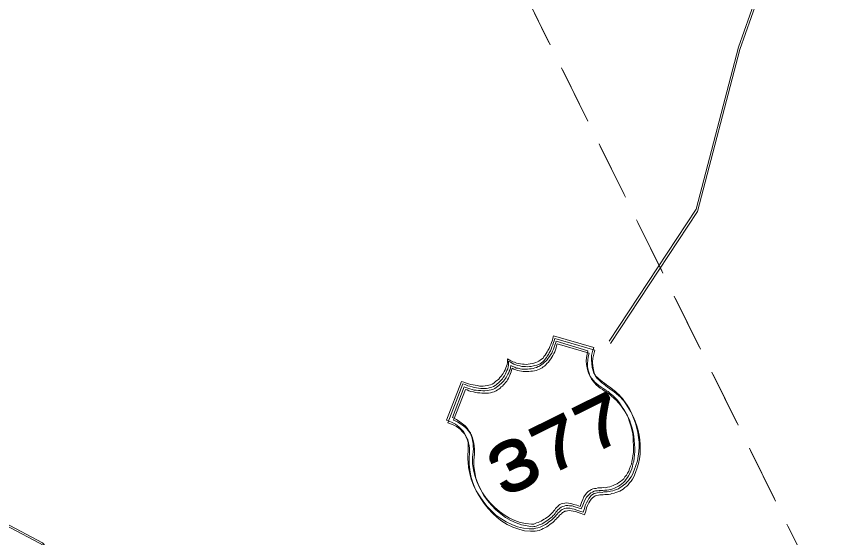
# Model space of a CAD drawing. Extents: x 2356606 to 2371222, y 6973096 to 6982644.
# Drawn here: x 2357158.9 to 2357247.4, y 6973509.1 to 6973564.3 of the extents above; entities that cross this region are included whole.
import ezdxf

# ---------------------------------------------------------------- set-up
doc = ezdxf.new("R2010")
doc.units = 0
doc.header["$LTSCALE"] = 2
doc.linetypes.add('MEDIUM_DASHED', pattern=[4.5, 3, -1.5])
doc.layers.add('62', color=7, linetype='Continuous', lineweight=13)
doc.layers.add('63', color=7, linetype='Continuous', lineweight=13)

msp = doc.modelspace()

# ---------------------------------------------------------------- linework, layer by layer
at = {"layer": '62', "linetype": 'MEDIUM_DASHED'}
msp.add_line((2357160.992, 6973671.606), (2357243.202, 6973505.087), dxfattribs=at)
at = {"layer": '62'}
msp.add_line((2357231.053, 6973543.631), (2357221.833, 6973529.622), dxfattribs=at)
for points in [[(2357247.334, 6973598.086), (2357243.665, 6973587.068), (2357241.545, 6973577.843), (2357235.54, 6973560.823), (2357231.053, 6973543.631)], [(2357204.57, 6973521.226), (2357206.171, 6973525.353), (2357206.412, 6973525.271), (2357206.693, 6973525.158), (2357206.923, 6973525.098), (2357207.155, 6973525.035), (2357207.386, 6973524.974), (2357207.629, 6973524.942), (2357207.849, 6973524.903), (2357208.071, 6973524.859), (2357208.273, 6973524.858), (2357208.473, 6973524.859), (2357208.692, 6973524.867), (2357208.875, 6973524.907), (2357209.076, 6973524.956), (2357209.237, 6973524.987), (2357209.419, 6973525.074), (2357209.6, 6973525.165), (2357209.702, 6973525.265), (2357209.824, 6973525.375), (2357209.975, 6973525.476), (2357210.117, 6973525.595), (2357210.239, 6973525.755), (2357210.37, 6973525.896), (2357210.471, 6973526.044), (2357210.593, 6973526.204), (2357210.695, 6973526.407), (2357210.787, 6973526.579), (2357210.857, 6973526.789), (2357210.949, 6973526.96), (2357211.002, 6973527.16), (2357211.031, 6973527.35), (2357211.032, 6973527.551), (2357211.034, 6973527.754), (2357211.215, 6973527.641), (2357211.414, 6973527.54), (2357211.594, 6973527.428), (2357211.798, 6973527.377), (2357211.988, 6973527.294), (2357212.208, 6973527.255), (2357212.431, 6973527.212), (2357212.62, 6973527.18), (2357212.822, 6973527.182), (2357213.036, 6973527.16), (2357213.246, 6973527.19), (2357213.437, 6973527.206), (2357213.66, 6973527.269), (2357213.821, 6973527.296), (2357214.041, 6973527.356), (2357214.233, 6973527.424), (2357214.374, 6973527.495), (2357214.523, 6973527.594), (2357214.646, 6973527.703), (2357214.81, 6973527.835), (2357214.91, 6973527.985), (2357215.032, 6973528.145), (2357215.133, 6973528.297), (2357215.245, 6973528.478), (2357215.335, 6973528.647), (2357215.458, 6973528.859), (2357215.54, 6973529.05), (2357215.631, 6973529.268), (2357215.704, 6973529.482), (2357215.804, 6973529.732), (2357215.856, 6973529.932), (2357215.938, 6973530.173), (2357220.189, 6973528.935), (2357220.065, 6973528.522), (2357219.952, 6973528.091), (2357219.939, 6973527.657), (2357219.969, 6973527.244), (2357220.016, 6973526.84), (2357220.114, 6973526.487), (2357220.214, 6973526.236), (2357220.335, 6973526.045), (2357220.425, 6973525.913), (2357220.596, 6973525.77), (2357220.733, 6973525.641), (2357220.915, 6973525.476), (2357221.117, 6973525.323), (2357221.318, 6973525.174), (2357221.528, 6973525.002), (2357221.758, 6973524.839), (2357221.998, 6973524.654), (2357222.229, 6973524.493), (2357222.48, 6973524.289), (2357222.689, 6973524.118), (2357222.879, 6973523.936), (2357223.059, 6973523.724), (2357223.25, 6973523.541), (2357223.38, 6973523.328), (2357223.72, 6973522.846), (2357223.999, 6973522.381), (2357224.238, 6973521.897), (2357224.435, 6973521.393), (2357224.626, 6973520.908), (2357224.752, 6973520.395), (2357224.86, 6973519.923), (2357224.938, 6973519.407), (2357224.988, 6973518.903), (2357224.995, 6973518.38)], [(2357224.294, 6973517.156), (2357224.345, 6973517.459), (2357224.397, 6973517.811), (2357224.409, 6973518.193), (2357224.412, 6973518.544), (2357224.383, 6973518.958), (2357224.357, 6973519.37), (2357224.327, 6973519.781), (2357224.239, 6973520.217), (2357224.131, 6973520.639), (2357223.991, 6973521.073), (2357223.843, 6973521.527), (2357223.632, 6973521.95), (2357223.375, 6973522.375), (2357223.143, 6973522.737), (2357222.937, 6973523.061), (2357222.697, 6973523.344), (2357222.467, 6973523.606), (2357222.197, 6973523.849), (2357221.945, 6973524.052), (2357221.713, 6973524.265), (2357221.454, 6973524.438), (2357221.173, 6973524.6), (2357220.972, 6973524.75), (2357220.742, 6973524.913), (2357220.532, 6973525.085), (2357220.32, 6973525.257), (2357220.15, 6973525.452), (2357219.98, 6973525.644), (2357219.819, 6973525.866), (2357219.68, 6973526.148), (2357219.571, 6973526.472), (2357219.483, 6973526.805), (2357219.414, 6973527.148), (2357219.387, 6973527.509), (2357219.427, 6973527.88), (2357219.48, 6973528.234), (2357219.574, 6973528.605), (2357216.187, 6973529.619), (2357216.125, 6973529.387), (2357216.073, 6973529.185), (2357216.002, 6973528.977), (2357215.93, 6973528.765), (2357215.831, 6973528.564), (2357215.728, 6973528.363), (2357215.617, 6973528.184), (2357215.503, 6973528.003), (2357215.362, 6973527.833), (2357215.251, 6973527.652), (2357215.098, 6973527.5), (2357214.978, 6973527.391), (2357214.826, 6973527.242), (2357214.695, 6973527.151), (2357214.583, 6973527.072), (2357214.451, 6973526.982), (2357214.302, 6973526.931), (2357214.119, 6973526.841), (2357213.947, 6973526.782), (2357213.775, 6973526.723), (2357213.565, 6973526.693), (2357213.393, 6973526.685), (2357213.182, 6973526.657), (2357212.98, 6973526.658), (2357212.799, 6973526.668), (2357212.576, 6973526.659), (2357212.387, 6973526.69), (2357212.185, 6973526.741), (2357211.974, 6973526.763), (2357211.804, 6973526.854), (2357211.593, 6973526.924), (2357211.392, 6973527.026), (2357211.351, 6973526.806), (2357211.32, 6973526.615), (2357211.228, 6973526.443), (2357211.168, 6973526.263), (2357211.085, 6973526.124), (2357211.015, 6973525.963), (2357210.902, 6973525.781), (2357210.839, 6973525.65), (2357210.709, 6973525.511), (2357210.607, 6973525.361), (2357210.488, 6973525.249), (2357210.376, 6973525.12), (2357210.242, 6973525.03), (2357210.134, 6973524.901), (2357209.983, 6973524.799), (2357209.851, 6973524.71), (2357209.699, 6973524.611), (2357209.497, 6973524.511), (2357209.315, 6973524.472), (2357209.095, 6973524.413), (2357208.884, 6973524.384), (2357208.641, 6973524.365), (2357208.42, 6973524.356), (2357208.209, 6973524.377), (2357207.976, 6973524.389), (2357207.717, 6973524.41), (2357207.504, 6973524.431), (2357207.294, 6973524.501), (2357207.042, 6973524.554), (2357206.831, 6973524.624)], [(2357206.461, 6973524.769), (2357205.205, 6973521.516), (2357205.626, 6973521.322), (2357205.977, 6973521.067), (2357206.279, 6973520.863), (2357206.539, 6973520.643), (2357206.769, 6973520.381), (2357206.948, 6973520.117), (2357207.11, 6973519.894), (2357207.2, 6973519.612), (2357207.288, 6973519.33), (2357207.346, 6973519.057), (2357207.397, 6973518.752), (2357207.415, 6973518.462), (2357207.422, 6973518.189), (2357207.4, 6973517.877), (2357207.371, 6973517.588), (2357207.347, 6973517.275), (2357207.345, 6973516.619), (2357207.442, 6973515.967), (2357207.57, 6973515.351), (2357207.807, 6973514.717), (2357208.085, 6973514.103), (2357208.395, 6973513.524), (2357208.794, 6973512.97), (2357209.212, 6973512.474), (2357209.674, 6973512.001), (2357210.197, 6973511.555), (2357210.706, 6973511.179), (2357211.27, 6973510.854), (2357211.821, 6973510.6), (2357212.402, 6973510.385), (2357212.988, 6973510.273), (2357213.579, 6973510.188), (2357213.691, 6973510.219), (2357213.824, 6973510.208), (2357213.971, 6973510.257), (2357214.135, 6973510.335), (2357214.285, 6973510.385), (2357214.436, 6973510.436), (2357214.599, 6973510.516), (2357214.768, 6973510.625), (2357214.922, 6973510.726), (2357215.082, 6973510.805), (2357215.225, 6973510.925), (2357215.374, 6973511.025), (2357215.516, 6973511.144), (2357215.638, 6973511.255), (2357215.75, 6973511.385), (2357215.86, 6973511.463), (2357215.961, 6973511.616), (2357216.054, 6973511.736), (2357216.144, 6973511.855), (2357216.237, 6973511.975), (2357216.378, 6973512.096), (2357216.468, 6973512.167), (2357216.59, 6973512.276), (2357216.751, 6973512.356), (2357216.911, 6973512.385), (2357217.114, 6973512.434), (2357217.306, 6973512.453), (2357217.497, 6973512.423), (2357217.759, 6973512.402), (2357218.06, 6973512.299), (2357218.399, 6973512.217), (2357218.741, 6973512.084), (2357218.895, 6973512.486), (2357219.028, 6973512.828), (2357219.149, 6973513.088), (2357219.302, 6973513.339), (2357219.463, 6973513.519), (2357219.594, 6973513.659), (2357219.758, 6973513.788), (2357219.938, 6973513.879), (2357220.101, 6973513.96), (2357220.262, 6973513.988), (2357220.453, 6973514.006), (2357220.634, 6973514.047), (2357220.835, 6973514.046), (2357221.037, 6973514.043), (2357221.218, 6973514.084), (2357221.449, 6973514.072), (2357221.651, 6973514.123), (2357221.885, 6973514.16), (2357222.076, 6973514.23), (2357222.265, 6973514.298), (2357222.467, 6973514.399), (2357222.67, 6973514.499), (2357222.844, 6973514.609), (2357223.034, 6973514.729), (2357223.205, 6973514.888), (2357223.368, 6973515.019), (2357223.489, 6973515.23), (2357223.65, 6973515.41), (2357223.754, 6973515.611), (2357223.895, 6973515.83), (2357223.996, 6973516.083), (2357224.089, 6973516.352), (2357224.181, 6973516.576), (2357224.213, 6973516.867), (2357224.294, 6973517.156)], [(2357206.831, 6973524.624), (2357206.641, 6973524.708), (2357206.461, 6973524.769)], [(2357205.523, 6973520.817), (2357205.093, 6973521.033), (2357204.57, 6973521.226)], [(2357224.995, 6973518.38), (2357224.983, 6973517.897), (2357224.898, 6973517.405), (2357224.817, 6973516.914), (2357224.652, 6973516.431), (2357224.488, 6973515.949), (2357224.295, 6973515.477), (2357224.162, 6973515.235), (2357224.031, 6973515.045), (2357223.858, 6973514.835), (2357223.698, 6973514.653), (2357223.556, 6973514.485), (2357223.363, 6973514.365), (2357223.171, 6973514.195), (2357223, 6973514.084), (2357222.808, 6973513.966), (2357222.596, 6973513.884), (2357222.405, 6973513.817), (2357222.214, 6973513.747), (2357221.981, 6973513.708), (2357221.83, 6973513.658), (2357221.619, 6973513.627), (2357221.417, 6973513.63), (2357221.245, 6973513.621), (2357221.067, 6973513.581), (2357220.885, 6973513.592), (2357220.716, 6973513.583), (2357220.562, 6973513.534), (2357220.4, 6973513.503), (2357220.219, 6973513.465), (2357220.067, 6973513.365), (2357219.925, 6973513.245), (2357219.794, 6973513.106), (2357219.661, 6973512.914), (2357219.55, 6973512.732), (2357219.409, 6973512.462), (2357219.285, 6973512.201), (2357219.204, 6973511.86), (2357219.07, 6973511.468), (2357218.73, 6973511.6), (2357218.408, 6973511.692), (2357218.128, 6973511.804), (2357217.885, 6973511.836), (2357217.653, 6973511.898), (2357217.454, 6973511.9), (2357217.282, 6973511.891), (2357217.12, 6973511.861), (2357217.01, 6973511.832), (2357216.848, 6973511.752), (2357216.747, 6973511.7), (2357216.636, 6973511.572), (2357216.525, 6973511.49), (2357216.414, 6973511.412), (2357216.314, 6973511.262), (2357216.189, 6973511.15), (2357216.12, 6973511.041), (2357215.978, 6973510.922), (2357215.848, 6973510.779), (2357215.717, 6973510.641), (2357215.545, 6973510.529), (2357215.393, 6973510.432), (2357215.24, 6973510.28), (2357215.07, 6973510.172), (2357214.868, 6973510.07), (2357214.706, 6973509.993), (2357214.503, 6973509.892), (2357214.272, 6973509.801), (2357214.06, 6973509.774), (2357213.84, 6973509.714), (2357213.588, 6973509.715), (2357213.337, 6973509.716), (2357212.733, 6973509.77), (2357212.098, 6973509.936), (2357211.486, 6973510.159), (2357210.895, 6973510.444), (2357210.323, 6973510.789), (2357209.812, 6973511.164), (2357209.331, 6973511.629), (2357208.861, 6973512.124), (2357208.452, 6973512.651), (2357208.081, 6973513.194), (2357207.732, 6973513.751), (2357207.443, 6973514.337), (2357207.204, 6973514.971), (2357207.037, 6973515.566), (2357206.91, 6973516.231), (2357206.86, 6973516.834), (2357206.844, 6973517.074), (2357206.835, 6973517.346), (2357206.855, 6973517.607), (2357206.889, 6973517.9), (2357206.87, 6973518.193), (2357206.87, 6973518.495), (2357206.862, 6973518.818), (2357206.794, 6973519.109), (2357206.693, 6973519.414), (2357206.544, 6973519.715), (2357206.396, 6973520.02), (2357206.144, 6973520.273), (2357205.884, 6973520.547), (2357205.523, 6973520.817)], [(2357140.286, 6973519.132), (2357145.727, 6973516.698), (2357161.735, 6973508.214), (2357173.541, 6973495.07), (2357183.025, 6973484.445), (2357194.164, 6973480.584), (2357213.862, 6973475.045), (2357224.711, 6973473.248), (2357242.083, 6973470.23), (2357259.834, 6973460.297)]]:
    msp.add_lwpolyline(points, dxfattribs=at)
at = {"layer": '63', "linetype": 'MEDIUM_DASHED'}
msp.add_line((2357160.862, 6973671.869), (2357243.072, 6973505.35), dxfattribs=at)
at = {"layer": '63'}
msp.add_line((2357230.923, 6973543.894), (2357221.703, 6973529.885), dxfattribs=at)
for points in [[(2357247.204, 6973598.349), (2357243.535, 6973587.331), (2357241.415, 6973578.106), (2357235.41, 6973561.086), (2357230.923, 6973543.894)], [(2357204.44, 6973521.489), (2357206.041, 6973525.616), (2357206.282, 6973525.534), (2357206.563, 6973525.421), (2357206.793, 6973525.361), (2357207.025, 6973525.298), (2357207.256, 6973525.237), (2357207.499, 6973525.205), (2357207.719, 6973525.166), (2357207.941, 6973525.122), (2357208.143, 6973525.121), (2357208.343, 6973525.122), (2357208.562, 6973525.13), (2357208.745, 6973525.17), (2357208.946, 6973525.219), (2357209.107, 6973525.25), (2357209.289, 6973525.337), (2357209.47, 6973525.428), (2357209.572, 6973525.528), (2357209.694, 6973525.638), (2357209.845, 6973525.739), (2357209.987, 6973525.858), (2357210.109, 6973526.018), (2357210.24, 6973526.159), (2357210.341, 6973526.307), (2357210.463, 6973526.467), (2357210.565, 6973526.67), (2357210.657, 6973526.842), (2357210.727, 6973527.052), (2357210.819, 6973527.223), (2357210.872, 6973527.423), (2357210.901, 6973527.613), (2357210.902, 6973527.814), (2357210.904, 6973528.017), (2357211.085, 6973527.904), (2357211.284, 6973527.803), (2357211.464, 6973527.691), (2357211.668, 6973527.64), (2357211.858, 6973527.557), (2357212.078, 6973527.518), (2357212.301, 6973527.475), (2357212.49, 6973527.443), (2357212.692, 6973527.445), (2357212.906, 6973527.423), (2357213.116, 6973527.453), (2357213.307, 6973527.469), (2357213.53, 6973527.532), (2357213.691, 6973527.559), (2357213.911, 6973527.619), (2357214.103, 6973527.687), (2357214.244, 6973527.758), (2357214.393, 6973527.857), (2357214.516, 6973527.966), (2357214.68, 6973528.098), (2357214.78, 6973528.248), (2357214.902, 6973528.408), (2357215.003, 6973528.56), (2357215.115, 6973528.741), (2357215.205, 6973528.91), (2357215.328, 6973529.122), (2357215.41, 6973529.313), (2357215.501, 6973529.531), (2357215.574, 6973529.745), (2357215.674, 6973529.995), (2357215.726, 6973530.195), (2357215.808, 6973530.436), (2357220.059, 6973529.198), (2357219.935, 6973528.785), (2357219.822, 6973528.354), (2357219.809, 6973527.92), (2357219.839, 6973527.507), (2357219.886, 6973527.103), (2357219.984, 6973526.75), (2357220.084, 6973526.499), (2357220.205, 6973526.308), (2357220.295, 6973526.176), (2357220.466, 6973526.033), (2357220.603, 6973525.904), (2357220.785, 6973525.739), (2357220.987, 6973525.586), (2357221.188, 6973525.437), (2357221.398, 6973525.265), (2357221.628, 6973525.102), (2357221.868, 6973524.917), (2357222.099, 6973524.756), (2357222.35, 6973524.552), (2357222.559, 6973524.381), (2357222.749, 6973524.199), (2357222.929, 6973523.987), (2357223.12, 6973523.804), (2357223.25, 6973523.591), (2357223.59, 6973523.109), (2357223.869, 6973522.644), (2357224.108, 6973522.16), (2357224.305, 6973521.656), (2357224.496, 6973521.171), (2357224.622, 6973520.658), (2357224.73, 6973520.186), (2357224.808, 6973519.67), (2357224.858, 6973519.166), (2357224.865, 6973518.643)], [(2357224.164, 6973517.419), (2357224.215, 6973517.722), (2357224.267, 6973518.074), (2357224.279, 6973518.456), (2357224.282, 6973518.807), (2357224.253, 6973519.221), (2357224.227, 6973519.633), (2357224.197, 6973520.044), (2357224.109, 6973520.48), (2357224.001, 6973520.902), (2357223.861, 6973521.336), (2357223.713, 6973521.79), (2357223.502, 6973522.213), (2357223.245, 6973522.638), (2357223.013, 6973523), (2357222.807, 6973523.324), (2357222.567, 6973523.607), (2357222.337, 6973523.869), (2357222.067, 6973524.112), (2357221.815, 6973524.315), (2357221.583, 6973524.528), (2357221.324, 6973524.701), (2357221.043, 6973524.863), (2357220.842, 6973525.013), (2357220.612, 6973525.176), (2357220.402, 6973525.348), (2357220.19, 6973525.52), (2357220.02, 6973525.715), (2357219.85, 6973525.907), (2357219.689, 6973526.129), (2357219.55, 6973526.411), (2357219.441, 6973526.735), (2357219.353, 6973527.068), (2357219.284, 6973527.411), (2357219.257, 6973527.772), (2357219.297, 6973528.143), (2357219.35, 6973528.497), (2357219.444, 6973528.868), (2357216.057, 6973529.882), (2357215.995, 6973529.65), (2357215.943, 6973529.448), (2357215.872, 6973529.24), (2357215.8, 6973529.028), (2357215.701, 6973528.827), (2357215.598, 6973528.626), (2357215.487, 6973528.447), (2357215.373, 6973528.266), (2357215.232, 6973528.096), (2357215.121, 6973527.915), (2357214.968, 6973527.763), (2357214.848, 6973527.654), (2357214.696, 6973527.505), (2357214.565, 6973527.414), (2357214.453, 6973527.335), (2357214.321, 6973527.245), (2357214.172, 6973527.194), (2357213.989, 6973527.104), (2357213.817, 6973527.045), (2357213.645, 6973526.986), (2357213.435, 6973526.956), (2357213.263, 6973526.948), (2357213.052, 6973526.92), (2357212.85, 6973526.921), (2357212.669, 6973526.931), (2357212.446, 6973526.922), (2357212.257, 6973526.953), (2357212.055, 6973527.004), (2357211.844, 6973527.026), (2357211.674, 6973527.117), (2357211.463, 6973527.187), (2357211.262, 6973527.289), (2357211.221, 6973527.069), (2357211.19, 6973526.878), (2357211.098, 6973526.706), (2357211.038, 6973526.526), (2357210.955, 6973526.387), (2357210.885, 6973526.226), (2357210.772, 6973526.044), (2357210.709, 6973525.913), (2357210.579, 6973525.774), (2357210.477, 6973525.624), (2357210.358, 6973525.512), (2357210.246, 6973525.383), (2357210.112, 6973525.293), (2357210.004, 6973525.164), (2357209.853, 6973525.062), (2357209.721, 6973524.973), (2357209.569, 6973524.874), (2357209.367, 6973524.774), (2357209.185, 6973524.735), (2357208.965, 6973524.676), (2357208.754, 6973524.647), (2357208.511, 6973524.628), (2357208.29, 6973524.619), (2357208.079, 6973524.64), (2357207.846, 6973524.652), (2357207.587, 6973524.673), (2357207.374, 6973524.694), (2357207.164, 6973524.764), (2357206.912, 6973524.817), (2357206.701, 6973524.887)], [(2357206.331, 6973525.032), (2357205.075, 6973521.779), (2357205.496, 6973521.585), (2357205.847, 6973521.33), (2357206.149, 6973521.126), (2357206.409, 6973520.906), (2357206.639, 6973520.644), (2357206.818, 6973520.38), (2357206.98, 6973520.157), (2357207.07, 6973519.875), (2357207.158, 6973519.593), (2357207.216, 6973519.32), (2357207.267, 6973519.015), (2357207.285, 6973518.725), (2357207.292, 6973518.452), (2357207.27, 6973518.14), (2357207.241, 6973517.851), (2357207.217, 6973517.538), (2357207.215, 6973516.882), (2357207.312, 6973516.23), (2357207.44, 6973515.614), (2357207.677, 6973514.98), (2357207.955, 6973514.366), (2357208.265, 6973513.787), (2357208.664, 6973513.233), (2357209.082, 6973512.737), (2357209.544, 6973512.264), (2357210.067, 6973511.818), (2357210.576, 6973511.442), (2357211.14, 6973511.117), (2357211.691, 6973510.863), (2357212.272, 6973510.648), (2357212.858, 6973510.536), (2357213.449, 6973510.451), (2357213.561, 6973510.482), (2357213.694, 6973510.471), (2357213.841, 6973510.52), (2357214.005, 6973510.598), (2357214.155, 6973510.648), (2357214.306, 6973510.699), (2357214.469, 6973510.779), (2357214.638, 6973510.888), (2357214.792, 6973510.989), (2357214.952, 6973511.068), (2357215.095, 6973511.188), (2357215.244, 6973511.288), (2357215.386, 6973511.407), (2357215.508, 6973511.518), (2357215.62, 6973511.648), (2357215.73, 6973511.726), (2357215.831, 6973511.879), (2357215.924, 6973511.999), (2357216.014, 6973512.118), (2357216.107, 6973512.238), (2357216.248, 6973512.359), (2357216.338, 6973512.43), (2357216.46, 6973512.539), (2357216.621, 6973512.619), (2357216.781, 6973512.648), (2357216.984, 6973512.697), (2357217.176, 6973512.716), (2357217.367, 6973512.686), (2357217.629, 6973512.665), (2357217.93, 6973512.562), (2357218.269, 6973512.48), (2357218.611, 6973512.347), (2357218.765, 6973512.749), (2357218.898, 6973513.091), (2357219.019, 6973513.351), (2357219.172, 6973513.602), (2357219.333, 6973513.782), (2357219.464, 6973513.922), (2357219.628, 6973514.051), (2357219.808, 6973514.142), (2357219.971, 6973514.223), (2357220.132, 6973514.251), (2357220.323, 6973514.269), (2357220.504, 6973514.31), (2357220.705, 6973514.309), (2357220.907, 6973514.306), (2357221.088, 6973514.347), (2357221.319, 6973514.335), (2357221.521, 6973514.386), (2357221.755, 6973514.423), (2357221.946, 6973514.493), (2357222.135, 6973514.561), (2357222.337, 6973514.662), (2357222.54, 6973514.762), (2357222.714, 6973514.872), (2357222.904, 6973514.992), (2357223.075, 6973515.151), (2357223.238, 6973515.282), (2357223.359, 6973515.493), (2357223.52, 6973515.673), (2357223.624, 6973515.874), (2357223.765, 6973516.093), (2357223.866, 6973516.346), (2357223.959, 6973516.615), (2357224.051, 6973516.839), (2357224.083, 6973517.13), (2357224.164, 6973517.419)], [(2357206.701, 6973524.887), (2357206.511, 6973524.971), (2357206.331, 6973525.032)], [(2357205.393, 6973521.08), (2357204.963, 6973521.296), (2357204.44, 6973521.489)], [(2357224.865, 6973518.643), (2357224.853, 6973518.16), (2357224.768, 6973517.668), (2357224.687, 6973517.177), (2357224.522, 6973516.694), (2357224.358, 6973516.212), (2357224.165, 6973515.74), (2357224.032, 6973515.498), (2357223.901, 6973515.308), (2357223.728, 6973515.098), (2357223.568, 6973514.916), (2357223.426, 6973514.748), (2357223.233, 6973514.628), (2357223.041, 6973514.458), (2357222.87, 6973514.347), (2357222.678, 6973514.229), (2357222.466, 6973514.147), (2357222.275, 6973514.08), (2357222.084, 6973514.01), (2357221.851, 6973513.971), (2357221.7, 6973513.921), (2357221.489, 6973513.89), (2357221.287, 6973513.893), (2357221.115, 6973513.884), (2357220.937, 6973513.844), (2357220.755, 6973513.855), (2357220.586, 6973513.846), (2357220.432, 6973513.797), (2357220.27, 6973513.766), (2357220.089, 6973513.728), (2357219.937, 6973513.628), (2357219.795, 6973513.508), (2357219.664, 6973513.369), (2357219.531, 6973513.177), (2357219.42, 6973512.995), (2357219.279, 6973512.725), (2357219.155, 6973512.464), (2357219.074, 6973512.123), (2357218.94, 6973511.731), (2357218.6, 6973511.863), (2357218.278, 6973511.955), (2357217.998, 6973512.067), (2357217.755, 6973512.099), (2357217.523, 6973512.161), (2357217.324, 6973512.163), (2357217.152, 6973512.154), (2357216.99, 6973512.124), (2357216.88, 6973512.095), (2357216.718, 6973512.015), (2357216.617, 6973511.963), (2357216.506, 6973511.835), (2357216.395, 6973511.753), (2357216.284, 6973511.675), (2357216.184, 6973511.525), (2357216.059, 6973511.413), (2357215.99, 6973511.304), (2357215.848, 6973511.185), (2357215.718, 6973511.042), (2357215.587, 6973510.904), (2357215.415, 6973510.792), (2357215.263, 6973510.695), (2357215.11, 6973510.543), (2357214.94, 6973510.435), (2357214.738, 6973510.333), (2357214.576, 6973510.256), (2357214.373, 6973510.155), (2357214.142, 6973510.064), (2357213.93, 6973510.037), (2357213.71, 6973509.977), (2357213.458, 6973509.978), (2357213.207, 6973509.979), (2357212.603, 6973510.033), (2357211.968, 6973510.199), (2357211.356, 6973510.422), (2357210.765, 6973510.707), (2357210.193, 6973511.052), (2357209.682, 6973511.427), (2357209.201, 6973511.892), (2357208.731, 6973512.387), (2357208.322, 6973512.914), (2357207.951, 6973513.457), (2357207.602, 6973514.014), (2357207.313, 6973514.6), (2357207.074, 6973515.234), (2357206.907, 6973515.829), (2357206.78, 6973516.494), (2357206.73, 6973517.097), (2357206.714, 6973517.337), (2357206.705, 6973517.609), (2357206.725, 6973517.87), (2357206.759, 6973518.163), (2357206.74, 6973518.456), (2357206.74, 6973518.758), (2357206.732, 6973519.081), (2357206.664, 6973519.372), (2357206.563, 6973519.677), (2357206.414, 6973519.978), (2357206.266, 6973520.283), (2357206.014, 6973520.536), (2357205.754, 6973520.81), (2357205.393, 6973521.08)], [(2357140.156, 6973519.395), (2357145.597, 6973516.961), (2357161.605, 6973508.477), (2357173.411, 6973495.333), (2357182.895, 6973484.708), (2357194.034, 6973480.847), (2357213.732, 6973475.308), (2357224.581, 6973473.511), (2357241.953, 6973470.493), (2357259.704, 6973460.56)]]:
    msp.add_lwpolyline(points, dxfattribs=at)

# ---------------------------------------------------------------- texts
at = {"layer": '62', "width": 1.35}
msp.add_text('377', height=5.099, rotation=26.268, dxfattribs=at).set_placement((2357210.476, 6973513.173))
at = {"layer": '63', "width": 1.35}
msp.add_text('377', height=5.099, rotation=26.268, dxfattribs=at).set_placement((2357210.346, 6973513.437))

doc.saveas('drawing.dxf')
